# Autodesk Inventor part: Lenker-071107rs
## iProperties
Manager: Dr.-Ing. Roland Schröder
Company: www.Das-Entwicklungsbuero.de
Created: 2007-11
Part Number: Lenker-071107rs
Project: 11308
Document SubType Name: Modeling
Designer: rsc
Engineer: Dr.-Ing. Roland Schröder
Oberflächen: Ra 6,4
Toleranzen: ISO 2768 - m
Kanten: brechen
Author: rsc
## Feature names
1. Drehung1 [Revolution]
